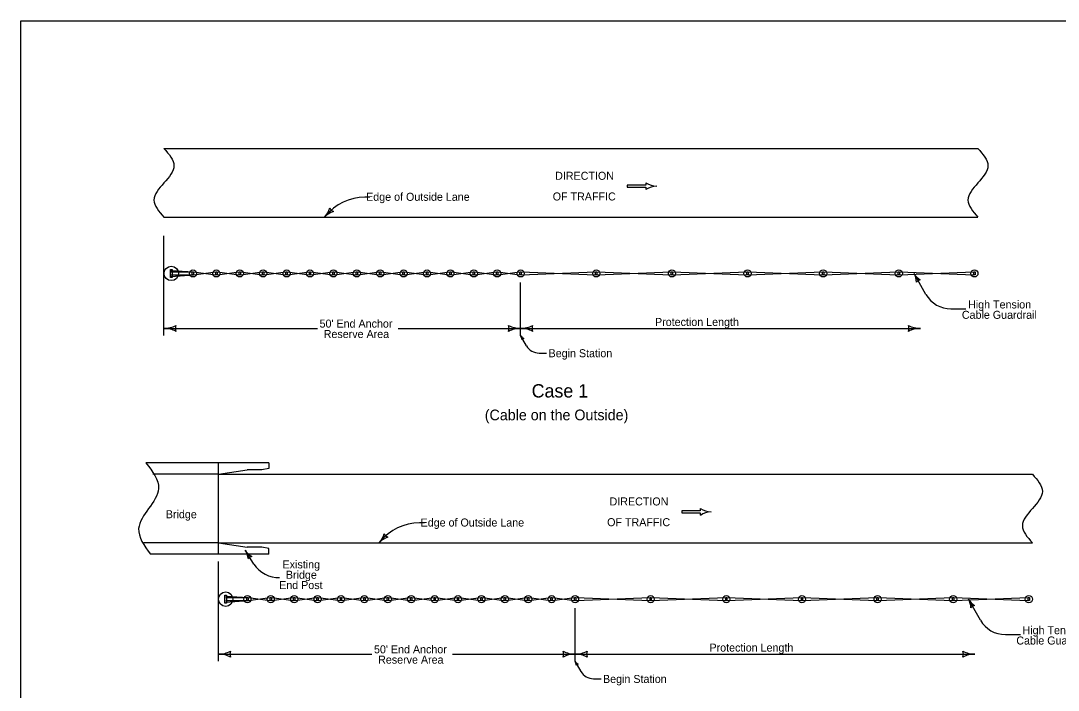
# Model space of a CAD drawing. Extents: x 10133 to 81668, y 7924 to 11018.
# Drawn here: x 10133 to 11688, y 8940 to 9944 of the extents above; entities that cross this region are included whole.
import ezdxf

# ---------------------------------------------------------------- set-up
doc = ezdxf.new("R2010")
doc.units = 0
for name, color, linetype in [('Default', 7, 'Continuous'), ('dsnCellElements', 7, 'Continuous'), ('DsnShtRevisedText', 7, 'Continuous'), ('dsnStdDimension', 7, 'Continuous'), ('Level 8', 7, 'Continuous'), ('SheetBorder', 7, 'Continuous')]:
    doc.layers.add(name, color=color, linetype=linetype)

msp = doc.modelspace()

# ---------------------------------------------------------------- linework, layer by layer
at = {"layer": 'Default'}
for p, q in [((10429, 9281.3), (10320.1, 9281.3)), ((10429, 9144.2), (10429, 9281.3)), ((10429, 9264.2), (10330.7, 9264.2)), ((10429, 9161.3), (10317.2, 9161.3)), ((10429, 9144.2), (10327, 9144.2))]:
    msp.add_line(p, q, dxfattribs=at)
msp.add_spline([(10320.1, 9281.3), (10339.3, 9242.8), (10324.3, 9212.8), (10309.3, 9182.8), (10327, 9144.2)], degree=3, dxfattribs=at)
at = {"layer": 'dsnCellElements'}
for p, q in [((10358.2, 9569.8), (10391.7, 9567.5)), ((10358.2, 9567.5), (10389.8, 9567.5)), ((10358.2, 9563), (10389.8, 9563)), ((10358.2, 9560.6), (10391.7, 9563)), ((10391.7, 9567.5), (10424.9, 9563)), ((10391.7, 9563), (10424.9, 9567.5)), ((10426.8, 9567.5), (10460, 9563)), ((10426.8, 9563), (10460, 9567.5)), ((10461.9, 9567.5), (10495.1, 9563)), ((10461.9, 9563), (10495.1, 9567.5)), ((10497, 9567.5), (10530.2, 9563)), ((10497, 9563), (10530.2, 9567.5)), ((10532.1, 9567.5), (10565.3, 9563)), ((10532.1, 9563), (10565.3, 9567.5)), ((10567.2, 9567.5), (10600.4, 9563)), ((10567.2, 9563), (10600.4, 9567.5)), ((10602.3, 9563), (10635.5, 9567.5)), ((10602.3, 9567.5), (10635.5, 9563)), ((10637.3, 9567.5), (10670.6, 9563)), ((10637.3, 9563), (10670.6, 9567.5)), ((10672.5, 9567.5), (10705.6, 9563)), ((10672.5, 9563), (10705.6, 9567.5)), ((10707.5, 9567.5), (10740.8, 9563)), ((10707.5, 9563), (10740.8, 9567.5)), ((10742.7, 9567.5), (10775.8, 9563)), ((10742.7, 9563), (10775.8, 9567.5)), ((10777.7, 9567.5), (10811, 9563)), ((10777.7, 9563), (10811, 9567.5)), ((10812.8, 9567.5), (10846, 9563)), ((10812.8, 9563), (10846, 9567.5)), ((10847.9, 9567.5), (10881.1, 9563)), ((10847.9, 9563), (10881.1, 9567.5)), ((10883, 9567.5), (10994.5, 9563)), ((10883, 9563), (10994.5, 9567.5)), ((10996.4, 9567.5), (11107.9, 9563)), ((10996.4, 9563), (11107.9, 9567.5)), ((11109.8, 9567.5), (11221.3, 9563)), ((11109.8, 9563), (11221.3, 9567.5)), ((11223.2, 9567.5), (11334.8, 9563)), ((11223.2, 9563), (11334.8, 9567.5)), ((11336.6, 9567.5), (11448.2, 9563)), ((11336.6, 9563), (11448.2, 9567.5)), ((11450, 9567.5), (11561.6, 9563)), ((11450, 9563), (11561.6, 9567.5)), ((10504.6, 9281.3), (10429, 9281.3)), ((10504.6, 9272.8), (10493.8, 9271)), ((10504.6, 9281.3), (10504.6, 9272.8)), ((10429, 9264.2), (10472.2, 9271)), ((10493.8, 9271), (10472.2, 9271)), ((10429, 9144.2), (10429, 9161.3)), ((10429, 9161.3), (10472.2, 9154.6)), ((10493.8, 9154.6), (10472.2, 9154.6)), ((10504.6, 9152.8), (10493.8, 9154.6)), ((10504.6, 9144.2), (10504.6, 9152.8)), ((10504.6, 9144.2), (10429, 9144.2)), ((10439.8, 9081.6), (10473.3, 9079.2)), ((10439.8, 9079.2), (10471.5, 9079.2)), ((10439.8, 9074.7), (10471.5, 9074.7)), ((10439.8, 9072.3), (10473.3, 9074.7)), ((10473.3, 9079.2), (10506.5, 9074.7)), ((10473.3, 9074.7), (10506.5, 9079.2)), ((10508.4, 9079.2), (10541.6, 9074.7)), ((10508.4, 9074.7), (10541.6, 9079.2)), ((10543.5, 9079.2), (10576.7, 9074.7)), ((10543.5, 9074.7), (10576.7, 9079.2)), ((10578.6, 9079.2), (10611.8, 9074.7)), ((10578.6, 9074.7), (10611.8, 9079.2)), ((10613.7, 9079.2), (10646.9, 9074.7)), ((10613.7, 9074.7), (10646.9, 9079.2)), ((10648.8, 9079.2), (10682, 9074.7)), ((10648.8, 9074.7), (10682, 9079.2)), ((10683.9, 9074.7), (10717.1, 9079.2)), ((10683.9, 9079.2), (10717.1, 9074.7)), ((10719, 9079.2), (10752.2, 9074.7)), ((10719, 9074.7), (10752.2, 9079.2)), ((10754.1, 9079.2), (10787.3, 9074.7)), ((10754.1, 9074.7), (10787.3, 9079.2)), ((10789.1, 9079.2), (10822.4, 9074.7)), ((10789.1, 9074.7), (10822.4, 9079.2)), ((10824.3, 9079.2), (10857.4, 9074.7)), ((10824.3, 9074.7), (10857.4, 9079.2)), ((10859.3, 9079.2), (10892.6, 9074.7)), ((10859.3, 9074.7), (10892.6, 9079.2)), ((10894.5, 9079.2), (10927.6, 9074.7)), ((10894.5, 9074.7), (10927.6, 9079.2)), ((10929.5, 9079.2), (10962.8, 9074.7)), ((10929.5, 9074.7), (10962.8, 9079.2)), ((10964.6, 9079.2), (11076.2, 9074.7)), ((10964.6, 9074.7), (11076.2, 9079.2)), ((11078, 9079.2), (11189.6, 9074.7)), ((11078, 9074.7), (11189.6, 9079.2)), ((11191.4, 9079.2), (11303, 9074.7)), ((11191.4, 9074.7), (11303, 9079.2)), ((11304.8, 9079.2), (11416.4, 9074.7)), ((11304.8, 9074.7), (11416.4, 9079.2)), ((11418.2, 9079.2), (11529.8, 9074.7)), ((11418.2, 9074.7), (11529.8, 9079.2)), ((11531.6, 9079.2), (11643.2, 9074.7)), ((11531.6, 9074.7), (11643.2, 9079.2))]:
    msp.add_line(p, q, dxfattribs=at)
for points in [[(10357, 9559.2), (10357, 9571.2), (10359.4, 9571.2), (10359.4, 9559.2)], [(10389.8, 9563), (10389.8, 9567.5), (10391.7, 9567.5), (10391.7, 9563)], [(10424.9, 9563), (10424.9, 9567.5), (10426.8, 9567.5), (10426.8, 9563)], [(10460, 9563), (10460, 9567.5), (10461.9, 9567.5), (10461.9, 9563)], [(10495.1, 9563), (10495.1, 9567.5), (10497, 9567.5), (10497, 9563)], [(10530.2, 9563), (10530.2, 9567.5), (10532.1, 9567.5), (10532.1, 9563)], [(10565.3, 9563), (10565.3, 9567.5), (10567.2, 9567.5), (10567.2, 9563)], [(10600.4, 9563), (10600.4, 9567.5), (10602.3, 9567.5), (10602.3, 9563)], [(10635.5, 9563), (10635.5, 9567.5), (10637.3, 9567.5), (10637.3, 9563)], [(10670.6, 9563), (10670.6, 9567.5), (10672.5, 9567.5), (10672.5, 9563)], [(10705.6, 9563), (10705.6, 9567.5), (10707.5, 9567.5), (10707.5, 9563)], [(10740.8, 9563), (10740.8, 9567.5), (10742.7, 9567.5), (10742.7, 9563)], [(10775.8, 9563), (10775.8, 9567.5), (10777.7, 9567.5), (10777.7, 9563)], [(10811, 9563), (10811, 9567.5), (10812.8, 9567.5), (10812.8, 9563)], [(10846, 9563), (10846, 9567.5), (10847.9, 9567.5), (10847.9, 9563)], [(10881.1, 9563), (10881.1, 9567.5), (10883, 9567.5), (10883, 9563)], [(10881.1, 9563), (10881.1, 9567.5), (10883, 9567.5), (10883, 9563)], [(10994.5, 9563), (10994.5, 9567.5), (10996.4, 9567.5), (10996.4, 9563)], [(10994.5, 9563), (10994.5, 9567.5), (10996.4, 9567.5), (10996.4, 9563)], [(11107.9, 9563), (11107.9, 9567.5), (11109.8, 9567.5), (11109.8, 9563)], [(11107.9, 9563), (11107.9, 9567.5), (11109.8, 9567.5), (11109.8, 9563)], [(11221.3, 9563), (11221.3, 9567.5), (11223.2, 9567.5), (11223.2, 9563)], [(11221.3, 9563), (11221.3, 9567.5), (11223.2, 9567.5), (11223.2, 9563)], [(11334.8, 9563), (11334.8, 9567.5), (11336.6, 9567.5), (11336.6, 9563)], [(11334.8, 9563), (11334.8, 9567.5), (11336.6, 9567.5), (11336.6, 9563)], [(11448.2, 9563), (11448.2, 9567.5), (11450, 9567.5), (11450, 9563)], [(11448.2, 9563), (11448.2, 9567.5), (11450, 9567.5), (11450, 9563)], [(11561.6, 9563), (11561.6, 9567.5), (11563.4, 9567.5), (11563.4, 9563)], [(10438.6, 9070.9), (10438.6, 9083), (10441, 9083), (10441, 9070.9)], [(10471.4, 9074.7), (10471.4, 9079.2), (10473.3, 9079.2), (10473.3, 9074.7)], [(10506.5, 9074.7), (10506.5, 9079.2), (10508.4, 9079.2), (10508.4, 9074.7)], [(10541.7, 9074.7), (10541.7, 9079.2), (10543.5, 9079.2), (10543.5, 9074.7)], [(10576.7, 9074.7), (10576.7, 9079.2), (10578.6, 9079.2), (10578.6, 9074.7)], [(10611.9, 9074.7), (10611.9, 9079.2), (10613.7, 9079.2), (10613.7, 9074.7)], [(10646.9, 9074.7), (10646.9, 9079.2), (10648.8, 9079.2), (10648.8, 9074.7)], [(10682, 9074.7), (10682, 9079.2), (10683.9, 9079.2), (10683.9, 9074.7)], [(10717.1, 9074.7), (10717.1, 9079.2), (10719, 9079.2), (10719, 9074.7)], [(10752.2, 9074.7), (10752.2, 9079.2), (10754.1, 9079.2), (10754.1, 9074.7)], [(10787.3, 9074.7), (10787.3, 9079.2), (10789.1, 9079.2), (10789.1, 9074.7)], [(10822.4, 9074.7), (10822.4, 9079.2), (10824.3, 9079.2), (10824.3, 9074.7)], [(10857.4, 9074.7), (10857.4, 9079.2), (10859.3, 9079.2), (10859.3, 9074.7)], [(10892.6, 9074.7), (10892.6, 9079.2), (10894.5, 9079.2), (10894.5, 9074.7)], [(10927.6, 9074.7), (10927.6, 9079.2), (10929.5, 9079.2), (10929.5, 9074.7)], [(10962.8, 9074.7), (10962.8, 9079.2), (10964.6, 9079.2), (10964.6, 9074.7)], [(10962.8, 9074.7), (10962.8, 9079.2), (10964.6, 9079.2), (10964.6, 9074.7)], [(11076.2, 9074.7), (11076.2, 9079.2), (11078, 9079.2), (11078, 9074.7)], [(11076.2, 9074.7), (11076.2, 9079.2), (11078, 9079.2), (11078, 9074.7)], [(11189.6, 9074.7), (11189.6, 9079.2), (11191.4, 9079.2), (11191.4, 9074.7)], [(11189.6, 9074.7), (11189.6, 9079.2), (11191.4, 9079.2), (11191.4, 9074.7)], [(11303, 9074.7), (11303, 9079.2), (11304.8, 9079.2), (11304.8, 9074.7)], [(11303, 9074.7), (11303, 9079.2), (11304.8, 9079.2), (11304.8, 9074.7)], [(11416.4, 9074.7), (11416.4, 9079.2), (11418.2, 9079.2), (11418.2, 9074.7)], [(11416.4, 9074.7), (11416.4, 9079.2), (11418.2, 9079.2), (11418.2, 9074.7)], [(11529.8, 9074.7), (11529.8, 9079.2), (11531.6, 9079.2), (11531.6, 9074.7)], [(11529.8, 9074.7), (11529.8, 9079.2), (11531.6, 9079.2), (11531.6, 9074.7)], [(11643.2, 9074.7), (11643.2, 9079.2), (11645, 9079.2), (11645, 9074.7)]]:
    msp.add_lwpolyline(points, close=True, dxfattribs=at)
for centre, radius in [((10358.2, 9565.2), 10.8), ((10390.8, 9565.2), 5.32), ((10425.8, 9565.2), 5.32), ((10461, 9565.2), 5.32), ((10496, 9565.2), 5.32), ((10531.2, 9565.2), 5.32), ((10566.2, 9565.2), 5.32), ((10601.4, 9565.2), 5.32), ((10636.4, 9565.2), 5.32), ((10671.5, 9565.2), 5.32), ((10706.6, 9565.2), 5.32), ((10741.7, 9565.2), 5.32), ((10776.8, 9565.2), 5.32), ((10811.9, 9565.2), 5.32), ((10846.9, 9565.2), 5.32), ((10882.1, 9565.2), 5.32), ((10882.1, 9565.2), 5.32), ((10995.5, 9565.2), 5.32), ((10995.5, 9565.2), 5.32), ((11108.9, 9565.2), 5.32), ((11108.9, 9565.2), 5.32), ((11222.3, 9565.2), 5.32), ((11222.3, 9565.2), 5.32), ((11335.7, 9565.2), 5.32), ((11335.7, 9565.2), 5.32), ((11449.1, 9565.2), 5.32), ((11449.1, 9565.2), 5.32), ((11562.5, 9565.2), 5.32), ((10439.8, 9076.9), 10.8), ((10472.4, 9076.9), 5.32), ((10507.4, 9076.9), 5.32), ((10542.6, 9076.9), 5.32), ((10577.6, 9076.9), 5.32), ((10612.8, 9076.9), 5.32), ((10647.8, 9076.9), 5.32), ((10683, 9076.9), 5.32), ((10718, 9076.9), 5.32), ((10753.2, 9076.9), 5.32), ((10788.2, 9076.9), 5.32), ((10823.3, 9076.9), 5.32), ((10858.4, 9076.9), 5.32), ((10893.5, 9076.9), 5.32), ((10928.6, 9076.9), 5.32), ((10963.7, 9076.9), 5.32), ((10963.7, 9076.9), 5.32), ((11077.1, 9076.9), 5.32), ((11077.1, 9076.9), 5.32), ((11190.5, 9076.9), 5.32), ((11190.5, 9076.9), 5.32), ((11303.9, 9076.9), 5.32), ((11303.9, 9076.9), 5.32), ((11417.3, 9076.9), 5.32), ((11417.3, 9076.9), 5.32), ((11530.7, 9076.9), 5.32), ((11530.7, 9076.9), 5.32), ((11644.1, 9076.9), 5.32)]:
    msp.add_circle(centre, radius, dxfattribs=at)
at = {"layer": 'DsnShtRevisedText'}
for p, q in [((11069.9, 9697.4), (11042, 9697.4)), ((11042, 9697.4), (11042, 9694.4)), ((11042, 9694.4), (11069.9, 9694.4)), ((11069.9, 9701), (11069.9, 9697.4)), ((11069.9, 9694.4), (11069.9, 9690.8)), ((11086.1, 9695.9), (11086.1, 9695.9)), ((10656.2, 9679.5), (10648.7, 9679.5)), ((10347.3, 9472.3), (10347.3, 9621.7)), ((11489.7, 9533.7), (11472, 9565)), ((10882.1, 9472.3), (10882.1, 9551.6)), ((11527.3, 9512), (11549.8, 9512)), ((10347.3, 9482.8), (10577.5, 9482.8)), ((10698.5, 9482.8), (10925, 9482.8)), ((10925, 9482.8), (11093, 9482.8)), ((11093, 9482.8), (11481.6, 9482.8)), ((10891, 9456.7), (10882.1, 9472.3)), ((10909.8, 9445.9), (10921, 9445.9)), ((11151.5, 9212.7), (11151.5, 9209.2)), ((11151.5, 9209.2), (11123.6, 9209.2)), ((11123.6, 9209.2), (11123.6, 9206.1)), ((11123.6, 9206.1), (11151.5, 9206.1)), ((11151.5, 9206.1), (11151.5, 9202.6)), ((11167.7, 9207.6), (11167.7, 9207.6)), ((10737.8, 9191.2), (10730.4, 9191.2)), ((10482.2, 9129.4), (10469.3, 9150.1)), ((10429, 8984.1), (10429, 9133.5)), ((11571.4, 9045.4), (11553.6, 9076.7)), ((10963.7, 8984.1), (10963.7, 9063.3)), ((11609, 9023.8), (11631.5, 9023.8)), ((10429, 8994.6), (10659.1, 8994.6)), ((10780.1, 8994.6), (11006.6, 8994.6)), ((11006.6, 8994.6), (11174.6, 8994.6)), ((11174.6, 8994.6), (11563.2, 8994.6)), ((10972.6, 8968.4), (10963.7, 8984.1)), ((10991.4, 8957.6), (11002.6, 8957.6))]:
    msp.add_line(p, q, dxfattribs=at)
for centre, radius, start, end in [((11087.4, 9728.6), 32.7, 237.618, 267.648), ((11087.4, 9663.2), 32.7, 92.352, 122.382), ((10648.7, 9603.3), 76.2, 90, 140.9894), ((10564.5, 9671.7), 32.4, 317.0027, 345.0752), ((10606.7, 9669.5), 12.5, 209.2694, 244.7361), ((10611.9, 9627.5), 32.4, 108.9302, 137.0027), ((11448.5, 9551.3), 27.2, 2.1589, 30.2314), ((11495.5, 9578.6), 27.2, 210.2314, 238.3038), ((11483.5, 9545.2), 10.5, 102.498, 137.9647), ((11527.3, 9555.6), 43.5, 210.2243, 270), ((10347.3, 9521.1), 38.3, 270, 298.0725), ((10347.3, 9444.6), 38.3, 61.9275, 90), ((10379.4, 9482.8), 14.8, 162.2666, 197.7334), ((10850, 9482.8), 14.8, 342.2666, 17.7333), ((10882.1, 9521.1), 38.3, 241.9275, 270), ((10882.1, 9444.6), 38.3, 90, 118.0725), ((10882.1, 9521.1), 38.3, 270, 298.0725), ((10882.1, 9444.6), 38.3, 61.9275, 90), ((10914.2, 9482.8), 14.8, 162.2666, 197.7334), ((11449.5, 9482.8), 14.8, 342.2666, 17.7333), ((11481.6, 9521.1), 38.3, 241.9275, 270), ((11481.6, 9444.6), 38.3, 90, 118.0725), ((10870.3, 9465.5), 13.6, 2.1589, 30.2314), ((10893.8, 9479.2), 13.6, 210.2314, 238.3038), ((10887.8, 9462.5), 5.25, 102.498, 137.9647), ((10909.8, 9467.6), 21.8, 210.2243, 270), ((11169.1, 9240.4), 32.7, 237.618, 267.648), ((11169.1, 9174.9), 32.7, 92.352, 122.382), ((10730.4, 9115), 76.2, 90, 140.9894), ((10646.2, 9183.4), 32.4, 317.0027, 345.0752), ((10693.5, 9139.3), 32.4, 108.9302, 137.0027), ((10688.3, 9181.2), 12.5, 209.2694, 244.7361), ((10446.3, 9135.5), 27.2, 4.5066, 32.5791), ((10492.2, 9164.8), 27.2, 212.5791, 240.6516), ((10481.5, 9130.9), 10.5, 104.8458, 140.3125), ((10518.9, 9152.8), 43.5, 212.5721, 272.3478), ((11530.1, 9063), 27.2, 2.1589, 30.2314), ((11577.1, 9090.4), 27.2, 210.2314, 238.3038), ((11565.1, 9057), 10.5, 102.498, 137.9647), ((11609, 9067.3), 43.5, 210.2243, 270), ((10429, 9032.8), 38.3, 270, 298.0725), ((10429, 8956.3), 38.3, 61.9275, 90), ((10461, 8994.6), 14.8, 162.2666, 197.7334), ((10931.6, 8994.6), 14.8, 342.2666, 17.7333), ((10963.7, 9032.8), 38.3, 241.9275, 270), ((10963.7, 8956.3), 38.3, 90, 118.0725), ((10963.7, 9032.8), 38.3, 270, 298.0725), ((10963.7, 8956.3), 38.3, 61.9275, 90), ((10995.8, 8994.6), 14.8, 162.2666, 197.7334), ((11531.1, 8994.6), 14.8, 342.2666, 17.7333), ((11563.2, 9032.8), 38.3, 241.9275, 270), ((11563.2, 8956.3), 38.3, 90, 118.0725), ((10951.9, 8977.2), 13.6, 2.1589, 30.2314), ((10975.4, 8990.9), 13.6, 210.2314, 238.3038), ((10969.4, 8974.2), 5.25, 102.498, 137.9647), ((10991.4, 8979.4), 21.8, 210.2243, 270)]:
    msp.add_arc(centre, radius, start, end, dxfattribs=at)
at = {"layer": 'dsnStdDimension'}
for p, q in [((10347.3, 9752.5), (11567.8, 9752.5)), ((10347.3, 9649.6), (11567.8, 9649.6)), ((10429, 9264.2), (11649.4, 9264.2)), ((10429, 9161.3), (11649.4, 9161.3))]:
    msp.add_line(p, q, dxfattribs=at)
for points in [[(10347.3, 9752.5), (10362.3, 9726.8), (10347.3, 9701), (10332.3, 9675.3), (10347.3, 9649.6)], [(11567.8, 9752.5), (11582.8, 9726.8), (11567.8, 9701), (11552.8, 9675.3), (11567.8, 9649.6)], [(11649.4, 9264.2), (11664.4, 9238.5), (11649.4, 9212.8), (11634.4, 9187.1), (11649.4, 9161.3)]]:
    msp.add_spline(points, degree=3, dxfattribs=at)
at = {"layer": 'SheetBorder'}
msp.add_lwpolyline([(10132.5, 9944), (13267.5, 9944), (13267.5, 7924), (10132.5, 7924)], close=True, dxfattribs=at)

# ---------------------------------------------------------------- texts
at = {"layer": 'DsnShtRevisedText'}
for s, p in [('DIRECTION', (10933.8, 9705.6)), ('Edge of Outside Lane', (10650.4, 9674.1)), ('OF TRAFFIC', (10930.2, 9674.6)), ('High Tension', (11553, 9512.7)), ('Cable Guardrail', (11543.7, 9497.2)), ("50' End Anchor", (10580.6, 9484)), ('Protection Length', (11083.6, 9486.5)), ('Reserve Area', (10586.8, 9468.4)), ('Begin Station', (10924, 9439.6)), ('DIRECTION', (11015.4, 9217.4)), ('Bridge', (10350.1, 9198.2)), ('Edge of Outside Lane', (10732.1, 9185.8)), ('OF TRAFFIC', (11011.8, 9186.3)), ('Existing', (10525.1, 9123)), ('Bridge', (10530.1, 9107.5)), ('End Post', (10520, 9092)), ('High Tension', (11634.6, 9024.4)), ("50' End Anchor", (10662.2, 8995.7)), ('Protection Length', (11165.2, 8998.3)), ('Cable Guardrail', (11625.3, 9008.9)), ('Reserve Area', (10668.4, 8980.2)), ('Begin Station', (11005.6, 8951.3))]:
    msp.add_text(s, height=12, dxfattribs=at).set_placement(p)
at = {"layer": 'Level 8'}
for s, height, p in [('Case 1', 20, (10898.6, 9379.2)), ('(Cable on the Outside)', 16, (10828.3, 9345.1))]:
    msp.add_text(s, height=height, dxfattribs=at).set_placement(p)

doc.saveas('drawing.dxf')
